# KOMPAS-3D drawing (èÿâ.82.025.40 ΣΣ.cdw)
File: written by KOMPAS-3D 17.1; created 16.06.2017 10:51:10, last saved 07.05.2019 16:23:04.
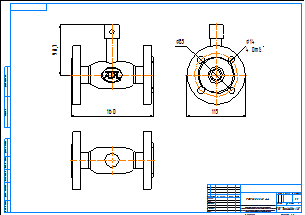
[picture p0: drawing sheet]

Sheet 1: A2, landscape

Title block, sheet 1: name: КШГ.82.025.40 фф; material: Внимание! Данный продукт является объектом авторского права ООО «Торговый Дом АДЛ». / Запрещается изменение, копирование, распространение / (в том числе путем копирования на другие сайты и ресурсы в Интернете) / или любое иное использование информации и объектов без предварительного / согласия правообладателя (ООО «Торговый Дом АДЛ»).; scale: 1:1; sheets: 1; organisation: ООО "Торговый дом АДЛ"; sheet format: A2; stored path: C:\Users\tra\Desktop\2д чертежи\Шаровые краны БИВАЛ\КШ_Бивал_серия_82_85\KOMPAS 2D\КШГ.82.025.40 фф.cdw

Views: Спереди 1, Проекционный вид 2, Проекционный вид 3
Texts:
  Klimkovich
  ADL
Dimensions and other numbers on the sheet: 160; 98,7; 115; 85; 14; 4 Отв.; 1:1; 1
